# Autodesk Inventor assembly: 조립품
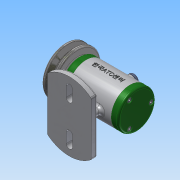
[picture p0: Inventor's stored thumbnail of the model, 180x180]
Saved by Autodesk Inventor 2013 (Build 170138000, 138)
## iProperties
Created: 2017-12
Part Number: 조립품
Document SubType Name: Assembly
Designer: Administrator
Author: Administrator
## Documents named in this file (14)
- C:\Users\Administrator\Desktop\471208V1003\조립품.iam
- C:\Users\Administrator\Desktop\471208V1003\본체.ipt
- C:\Users\Administrator\Desktop\471208V1003\V벨트풀리.ipt
- C:\Users\Administrator\Desktop\471208V1003\고무캡.ipt
- C:\Users\Administrator\Desktop\471208V1003\너트 M 8.ipt
- C:\Users\Administrator\Desktop\471208V1003\뒤커버.ipt
- C:\Users\Administrator\Desktop\471208V1003\베어링 15 x 32 x 9.ipt
- C:\Users\Administrator\Desktop\471208V1003\볼트 M4 x 12.ipt
- C:\Users\Administrator\Desktop\471208V1003\스프링와셔 8.ipt
- C:\Users\Administrator\Desktop\471208V1003\앞커버.ipt
- C:\Users\Administrator\Desktop\471208V1003\오일 실 15 25 7.ipt
- C:\Users\Administrator\Desktop\471208V1003\와셔 8x17.ipt
- C:\Users\Administrator\Desktop\471208V1003\축.ipt
- C:\Users\Administrator\Desktop\471208V1003\키 3 x 3 x 12.ipt
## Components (2 placed, 2 different names)
1. V벨트풀리:1
2. 고무캡:1
